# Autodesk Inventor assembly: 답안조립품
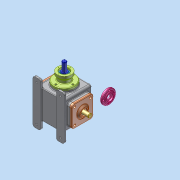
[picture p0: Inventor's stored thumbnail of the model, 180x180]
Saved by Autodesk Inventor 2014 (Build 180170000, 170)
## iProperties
Created: 2026-01
Part Number: 답안조립품
Document SubType Name: Assembly
Designer: dg
Author: dg
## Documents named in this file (12)
- C:\Users\dg\Desktop\760103V1003\답안조립품.iam
- C:\Users\dg\Desktop\760103V1003\본체.ipt
- C:\Users\dg\Desktop\760103V1003\가져온 구성요소\구동축\구동축.ipt
- C:\Users\dg\Desktop\760103V1003\가져온 구성요소\종동축\종동축.ipt
- C:\Users\dg\Desktop\760103V1003\가져온 구성요소\평행 키 6x6x18\평행 키 6x6x18.ipt
- C:\Users\dg\Desktop\760103V1003\가져온 구성요소\베벨 기어(구동)\베벨 기어(구동).ipt
- C:\Users\dg\Desktop\760103V1003\가져온 구성요소\베벨 기어(종동)\베벨 기어(종동).ipt
- C:\Users\dg\Desktop\760103V1003\가져온 구성요소\베어링 하우징\베어링 하우징.ipt
- C:\Users\dg\Desktop\760103V1003\가져온 구성요소\테이퍼 롤러 베어링 30204K\테이퍼 롤러 베어링 30204K.ipt
- C:\Users\dg\Desktop\760103V1003\가져온 구성요소\칼라\칼라.ipt
- C:\Users\dg\Desktop\760103V1003\가져온 구성요소\하우징 커버\하우징 커버.ipt
- C:\Users\dg\Desktop\760103V1003\가져온 구성요소\측면 커버\측면 커버.ipt
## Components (2 placed, 2 different names)
1. 구동축:1
2. 하우징 커버:1
